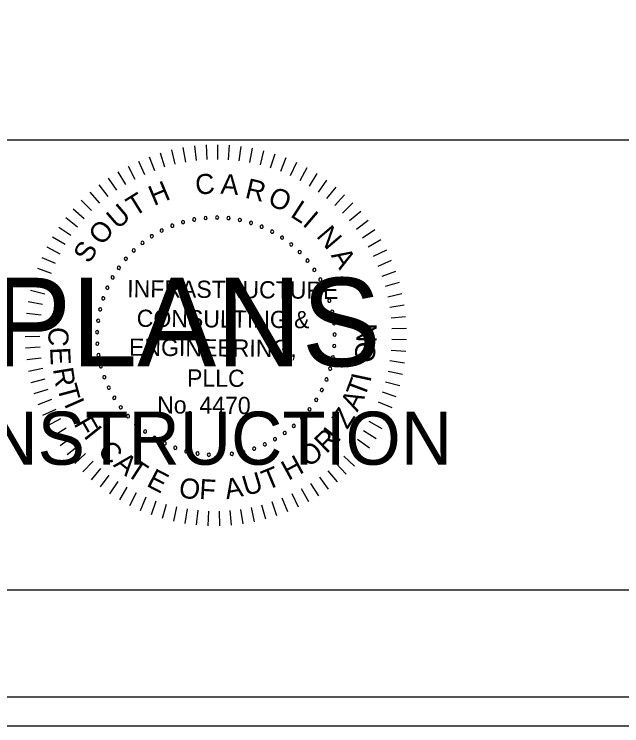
# Model space of a CAD drawing. Extents: x 967 to 1326, y 964 to 1744.
# Drawn here: x 1189.3 to 1212.88, y 963.72 to 991.36 of the extents above; entities that cross this region are included whole.
import ezdxf

# ---------------------------------------------------------------- set-up
doc = ezdxf.new("R2010")
doc.units = 0
for name, color, linetype in [('RD_PD_PaveShd', 7, 'Continuous'), ('RD_XS_Base', 7, 'Continuous'), ('RD_XS_CurbBase', 7, 'Continuous'), ('RD_XS_TieSlope', 7, 'Continuous'), ('RD_XS_TX_TOC', 7, 'Continuous')]:
    doc.layers.add(name, color=color, linetype=linetype)

msp = doc.modelspace()

# ---------------------------------------------------------------- linework, layer by layer
at = {"layer": 'RD_PD_PaveShd'}
for p, q in [((996.114, 986.486), (1323.886, 986.486)), ((1323.886, 968.983), (996.114, 968.983))]:
    msp.add_line(p, q, dxfattribs=at)
at = {"layer": 'RD_XS_CurbBase'}
msp.add_lwpolyline([(967.409, 963.72), (1326.285, 963.72), (1326.285, 1183.72), (967.409, 1183.72)], close=True, dxfattribs=at)
at = {"layer": 'RD_XS_TieSlope'}
for p, q in [((1196.292, 986.245), (1196.357, 985.68)), ((1196.742, 986.282), (1196.772, 985.714)), ((1197.194, 986.292), (1197.189, 985.723)), ((1197.645, 986.274), (1197.606, 985.706)), ((1198.094, 986.228), (1198.02, 985.664)), ((1194.968, 985.971), (1195.134, 985.427)), ((1195.403, 986.09), (1195.536, 985.536)), ((1195.846, 986.181), (1195.945, 985.62)), ((1198.54, 986.156), (1198.432, 985.596)), ((1198.98, 986.056), (1198.838, 985.504)), ((1199.414, 985.929), (1199.238, 985.387)), ((1194.122, 985.656), (1194.353, 985.136)), ((1194.54, 985.827), (1194.739, 985.293)), ((1199.839, 985.777), (1199.63, 985.246)), ((1193.715, 985.461), (1193.978, 984.956)), ((1200.253, 985.598), (1200.013, 985.082)), ((1200.656, 985.395), (1200.385, 984.894)), ((1193.321, 985.241), (1193.614, 984.752)), ((1201.047, 985.167), (1200.745, 984.684)), ((1192.94, 984.997), (1193.263, 984.528)), ((1201.422, 984.917), (1201.092, 984.453)), ((1192.576, 984.731), (1192.926, 984.282)), ((1201.781, 984.643), (1201.424, 984.2)), ((1192.228, 984.443), (1192.605, 984.016)), ((1202.124, 984.349), (1201.739, 983.928)), ((1191.899, 984.134), (1192.301, 983.731)), ((1202.447, 984.034), (1202.038, 983.638)), ((1191.589, 983.805), (1192.015, 983.428)), ((1202.751, 983.7), (1202.318, 983.329)), ((1191.299, 983.459), (1191.748, 983.108)), ((1203.034, 983.348), (1202.579, 983.004)), ((1191.032, 983.095), (1191.501, 982.772)), ((1203.294, 982.979), (1202.82, 982.664)), ((1190.787, 982.716), (1191.274, 982.422)), ((1203.532, 982.595), (1203.04, 982.31)), ((1190.565, 982.323), (1191.07, 982.059)), ((1203.746, 982.198), (1203.237, 981.943)), ((1190.368, 981.916), (1190.888, 981.684)), ((1203.936, 981.788), (1203.412, 981.564)), ((1190.196, 981.499), (1190.729, 981.299)), ((1204.1, 981.367), (1203.563, 981.176)), ((1190.05, 981.072), (1190.594, 980.905)), ((1204.238, 980.937), (1203.691, 980.779)), ((1189.93, 980.636), (1190.484, 980.503)), ((1204.349, 980.5), (1203.794, 980.375)), ((1189.837, 980.195), (1190.398, 980.095)), ((1204.434, 980.056), (1203.872, 979.966)), ((1189.771, 979.748), (1190.337, 979.683)), ((1204.491, 979.608), (1203.925, 979.552)), ((1189.732, 979.298), (1190.301, 979.267)), ((1204.522, 979.158), (1203.953, 979.137)), ((1189.721, 978.847), (1190.29, 978.851)), ((1204.524, 978.706), (1203.955, 978.72)), ((1189.737, 978.396), (1190.306, 978.434)), ((1204.499, 978.256), (1203.932, 978.304)), ((1189.781, 977.946), (1190.346, 978.019)), ((1204.447, 977.807), (1203.884, 977.89)), ((1189.852, 977.5), (1190.412, 977.608)), ((1204.367, 977.363), (1203.81, 977.479)), ((1189.951, 977.06), (1190.502, 977.201)), ((1204.261, 976.924), (1203.712, 977.074)), ((1190.076, 976.626), (1190.617, 976.8)), ((1204.128, 976.492), (1203.589, 976.676)), ((1190.227, 976.2), (1190.757, 976.408)), ((1203.969, 976.07), (1203.442, 976.286)), ((1190.403, 975.785), (1190.92, 976.024)), ((1203.784, 975.658), (1203.271, 975.906)), ((1190.605, 975.381), (1191.106, 975.651)), ((1203.574, 975.258), (1203.078, 975.537)), ((1190.831, 974.99), (1191.315, 975.291)), ((1203.341, 974.871), (1202.862, 975.18)), ((1191.081, 974.614), (1191.545, 974.943)), ((1191.353, 974.253), (1191.796, 974.61)), ((1203.085, 974.5), (1202.626, 974.837)), ((1202.806, 974.145), (1202.368, 974.509)), ((1191.646, 973.91), (1192.067, 974.293)), ((1202.506, 973.807), (1202.092, 974.197)), ((1191.96, 973.585), (1192.356, 973.994)), ((1202.186, 973.488), (1201.796, 973.903)), ((1192.293, 973.28), (1192.664, 973.712)), ((1201.847, 973.19), (1201.484, 973.628)), ((1192.644, 972.996), (1192.988, 973.45)), ((1193.011, 972.734), (1193.327, 973.208)), ((1201.491, 972.912), (1201.155, 973.372)), ((1193.394, 972.495), (1193.68, 972.987)), ((1200.731, 972.425), (1200.453, 972.922)), ((1201.119, 972.657), (1200.811, 973.136)), ((1193.791, 972.279), (1194.047, 972.788)), ((1200.331, 972.217), (1200.083, 972.73)), ((1194.2, 972.088), (1194.424, 972.612)), ((1194.62, 971.923), (1194.812, 972.459)), ((1199.495, 971.877), (1199.312, 972.416)), ((1199.918, 972.034), (1199.702, 972.561)), ((1195.05, 971.783), (1195.208, 972.33)), ((1195.487, 971.67), (1195.612, 972.225)), ((1195.93, 971.584), (1196.021, 972.146)), ((1196.377, 971.524), (1196.434, 972.091)), ((1198.179, 971.562), (1198.097, 972.126)), ((1198.624, 971.64), (1198.508, 972.198)), ((1199.063, 971.745), (1198.913, 972.295)), ((1196.828, 971.493), (1196.85, 972.062)), ((1197.279, 971.488), (1197.267, 972.058)), ((1197.73, 971.512), (1197.683, 972.079))]:
    msp.add_line(p, q, dxfattribs=at)
for centre, start, end in [((1196.285, 983.388), 10.6038, 190.6038), ((1196.727, 983.447), 5.0653, 185.0653), ((1196.727, 983.447), 185.0653, 5.0653), ((1197.172, 983.464), 359.5268, 179.5268), ((1197.172, 983.464), 179.5268, 359.5268), ((1197.617, 983.438), 173.9884, 353.9884), ((1197.617, 983.438), 353.9884, 173.9884), ((1198.057, 983.369), 348.4499, 168.4499), ((1195.429, 983.142), 21.6807, 201.6807), ((1195.429, 983.142), 201.6807, 21.6807), ((1195.851, 983.285), 16.1422, 196.1422), ((1195.851, 983.285), 196.1422, 16.1422), ((1196.285, 983.388), 190.6038, 10.6038), ((1198.057, 983.369), 168.4499, 348.4499), ((1198.489, 983.258), 162.9114, 342.9114), ((1198.489, 983.258), 342.9114, 162.9114), ((1198.908, 983.106), 337.373, 157.373), ((1195.023, 982.958), 27.2191, 207.2191), ((1195.023, 982.958), 207.2191, 27.2191), ((1198.908, 983.106), 157.373, 337.373), ((1199.31, 982.914), 151.8345, 331.8345), ((1199.31, 982.914), 331.8345, 151.8345), ((1194.637, 982.736), 32.7576, 212.7576), ((1194.637, 982.736), 212.7576, 32.7576), ((1199.692, 982.684), 146.2961, 326.2961), ((1199.692, 982.684), 326.2961, 146.2961), ((1194.274, 982.478), 38.2961, 218.2961), ((1194.274, 982.478), 218.2961, 38.2961), ((1200.05, 982.419), 140.7576, 320.7576), ((1200.05, 982.419), 320.7576, 140.7576), ((1193.937, 982.186), 43.8345, 223.8345), ((1193.937, 982.186), 223.8345, 43.8345), ((1200.38, 982.12), 135.2191, 315.2191), ((1200.38, 982.12), 315.2191, 135.2191), ((1193.63, 981.862), 49.373, 229.373), ((1193.63, 981.862), 229.373, 49.373), ((1200.68, 981.79), 129.6807, 309.6807), ((1200.68, 981.79), 309.6807, 129.6807), ((1193.356, 981.511), 54.9114, 234.9114), ((1193.356, 981.511), 234.9114, 54.9114), ((1200.947, 981.433), 304.1422, 124.1422), ((1200.947, 981.433), 124.1422, 304.1422), ((1193.117, 981.135), 60.4499, 240.4499), ((1193.117, 981.135), 240.4499, 60.4499), ((1201.179, 981.052), 118.6038, 298.6038), ((1201.179, 981.052), 298.6038, 118.6038), ((1192.915, 980.737), 65.9884, 245.9884), ((1192.915, 980.737), 245.9884, 65.9884), ((1201.372, 980.651), 113.0653, 293.0653), ((1201.372, 980.651), 293.0653, 113.0653), ((1192.753, 980.322), 71.5268, 251.5268), ((1192.753, 980.322), 251.5268, 71.5268), ((1201.526, 980.233), 107.5268, 287.5268), ((1201.526, 980.233), 287.5268, 107.5268), ((1192.632, 979.894), 77.0653, 257.0653), ((1192.632, 979.894), 257.0653, 77.0653), ((1201.638, 979.801), 101.9884, 281.9884), ((1201.638, 979.801), 281.9884, 101.9884), ((1192.552, 979.455), 82.6038, 262.6038), ((1192.552, 979.455), 262.6038, 82.6038), ((1201.709, 979.361), 96.4499, 276.4499), ((1201.709, 979.361), 276.4499, 96.4499), ((1192.515, 979.011), 88.1422, 268.1422), ((1192.515, 979.011), 268.1422, 88.1422), ((1201.737, 978.917), 90.9114, 270.9114), ((1201.737, 978.917), 270.9114, 90.9114), ((1192.522, 978.565), 93.6807, 273.6807), ((1192.522, 978.565), 273.6807, 93.6807), ((1201.721, 978.471), 85.373, 265.373), ((1201.721, 978.471), 265.373, 85.373), ((1192.571, 978.122), 99.2191, 279.2191), ((1192.571, 978.122), 279.2191, 99.2191), ((1201.663, 978.029), 79.8345, 259.8345), ((1201.663, 978.029), 259.8345, 79.8345), ((1192.662, 977.686), 104.7576, 284.7576), ((1192.662, 977.686), 284.7576, 104.7576), ((1201.563, 977.595), 74.2961, 254.2961), ((1201.563, 977.595), 254.2961, 74.2961), ((1192.796, 977.261), 110.2961, 290.2961), ((1192.796, 977.261), 290.2961, 110.2961), ((1201.42, 977.173), 68.7576, 248.7576), ((1201.42, 977.173), 248.7576, 68.7576), ((1192.97, 976.851), 115.8345, 295.8345), ((1192.97, 976.851), 295.8345, 115.8345), ((1201.238, 976.766), 63.2191, 243.2191), ((1201.238, 976.766), 243.2191, 63.2191), ((1193.182, 976.459), 301.373, 121.373), ((1193.182, 976.459), 121.373, 301.373), ((1201.018, 976.379), 57.6807, 237.6807), ((1201.018, 976.379), 237.6807, 57.6807), ((1193.432, 976.09), 126.9114, 306.9114), ((1193.432, 976.09), 306.9114, 126.9114), ((1200.761, 976.014), 52.1422, 232.1422), ((1200.761, 976.014), 232.1422, 52.1422), ((1193.715, 975.746), 132.4499, 312.4499), ((1193.715, 975.746), 312.4499, 132.4499), ((1200.47, 975.677), 46.6038, 226.6038), ((1200.47, 975.677), 226.6038, 46.6038), ((1194.031, 975.431), 137.9884, 317.9884), ((1194.031, 975.431), 317.9884, 137.9884), ((1200.148, 975.369), 41.0653, 221.0653), ((1200.148, 975.369), 221.0653, 41.0653), ((1194.376, 975.149), 143.5268, 323.5268), ((1194.376, 975.149), 323.5268, 143.5268), ((1199.798, 975.093), 35.5268, 215.5268), ((1194.746, 974.901), 149.0653, 329.0653), ((1194.746, 974.901), 329.0653, 149.0653), ((1199.422, 974.853), 29.9884, 209.9884), ((1199.422, 974.853), 209.9884, 29.9884), ((1199.798, 975.093), 215.5268, 35.5268), ((1195.139, 974.69), 154.6038, 334.6038), ((1195.139, 974.69), 334.6038, 154.6038), ((1195.55, 974.517), 340.1422, 160.1422), ((1199.026, 974.65), 24.4499, 204.4499), ((1199.026, 974.65), 204.4499, 24.4499), ((1195.55, 974.517), 160.1422, 340.1422), ((1195.975, 974.386), 165.6807, 345.6807), ((1195.975, 974.386), 345.6807, 165.6807), ((1196.412, 974.295), 171.2191, 351.2191), ((1196.412, 974.295), 351.2191, 171.2191), ((1196.855, 974.248), 356.7576, 176.7576), ((1197.301, 974.243), 2.2961, 182.2961), ((1197.745, 974.282), 7.8345, 187.8345), ((1198.183, 974.363), 13.373, 193.373), ((1198.183, 974.363), 193.373, 13.373), ((1198.611, 974.486), 18.9114, 198.9114), ((1198.611, 974.486), 198.9114, 18.9114), ((1196.855, 974.248), 176.7576, 356.7576), ((1197.301, 974.243), 182.2961, 2.2961), ((1197.745, 974.282), 187.8345, 7.8345)]:
    msp.add_arc(centre, 0.0627, start, end, dxfattribs=at)
at = {"layer": 'RD_XS_TX_TOC'}
for points in [[(967.409, 963.72), (1326.285, 963.72), (1326.285, 1183.72), (967.409, 1183.72)], [(988.525, 964.84), (1326.285, 964.84), (1326.285, 1182.6), (988.525, 1182.6)]]:
    msp.add_lwpolyline(points, close=True, dxfattribs=at)

# ---------------------------------------------------------------- texts
at = {"layer": 'RD_XS_Base'}
for s, height, p in [('FINAL PLANS', 3.4375, (1174.145, 977.685)), ('NOT FOR CONSTRUCTION', 2.0625, (1170.901, 973.86))]:
    msp.add_text(s, height=height, dxfattribs=at).set_placement(p)
at = {"layer": 'RD_XS_TieSlope'}
for s, height, rotation, p in [('C', 0.78, 4.7281, (1196.355, 984.346)), ('A', 0.78, 355.6981, (1197.29, 984.39)), ('H', 0.78, 22.7882, (1194.72, 983.904)), ('R', 0.78, 346.6681, (1198.222, 984.238)), ('O', 0.78, 337.638, (1199.096, 983.972)), ('T', 0.78, 31.8182, (1193.961, 983.478)), ('U', 0.78, 40.8482, (1193.306, 982.976)), ('L', 0.78, 327.108, (1199.981, 983.52)), ('I', 0.78, 319.578, (1200.451, 983.182)), ('O', 0.78, 49.8782, (1192.707, 982.341)), ('N', 0.78, 310.548, (1200.994, 982.728)), ('S', 0.78, 58.9083, (1192.211, 981.642)), ('A', 0.78, 301.5179, (1201.576, 981.991)), ('INFRASTRUCTURE', 0.66873, 359.5268, (1193.682, 980.367)), ('CONSULTING &', 0.66873, 359.5268, (1194.051, 979.217)), ('N', 0.78, 89.2085, (1203.359, 978.604)), ('C', 0.78, 267.025, (1190.646, 979.227)), ('ENGINEERING,', 0.66873, 359.5268, (1193.751, 978.095)), ('O', 0.78, 83.2085, (1203.26, 977.786)), ('E', 0.78, 273.025, (1190.685, 978.408)), ('R', 0.78, 279.025, (1190.799, 977.583)), ('PLLC', 0.6687, 359.5268, (1196.002, 976.9)), ('I', 0.78, 77.9093, (1203.121, 977.032)), ('T', 0.78, 69.3954, (1202.891, 976.428)), ('T', 0.78, 285.025, (1190.955, 976.878)), ('No. 4470', 0.6687, 359.5268, (1194.843, 975.855)), ('A', 0.78, 63.3954, (1202.616, 975.888)), ('I', 0.78, 293.7713, (1191.221, 976.225)), ('Z', 0.78, 57.3954, (1202.224, 975.206)), ('F', 0.78, 299.7713, (1191.589, 975.455)), ('I', 0.78, 308.5268, (1191.965, 974.973)), ('R', 0.78, 44.5268, (1201.415, 974.267)), ('I', 0.78, 52.3339, (1201.856, 974.69)), ('C', 0.78, 314.5268, (1192.496, 974.346)), ('O', 0.78, 38.5268, (1200.73, 973.731)), ('A', 0.78, 320.5268, (1193.115, 973.822)), ('T', 0.78, 326.5268, (1193.602, 973.478)), ('H', 0.78, 28.5268, (1199.942, 973.23)), ('T', 0.78, 22.5268, (1199.108, 972.856)), ('E', 0.78, 332.5268, (1194.394, 973.051)), ('U', 0.78, 16.5268, (1198.288, 972.638)), ('O', 0.78, 350.5268, (1195.647, 972.614)), ('F', 0.78, 356.5268, (1196.465, 972.532)), ('A', 0.78, 10.5268, (1197.537, 972.517))]:
    msp.add_text(s, height=height, rotation=rotation, dxfattribs=at).set_placement(p)

doc.saveas('drawing.dxf')
